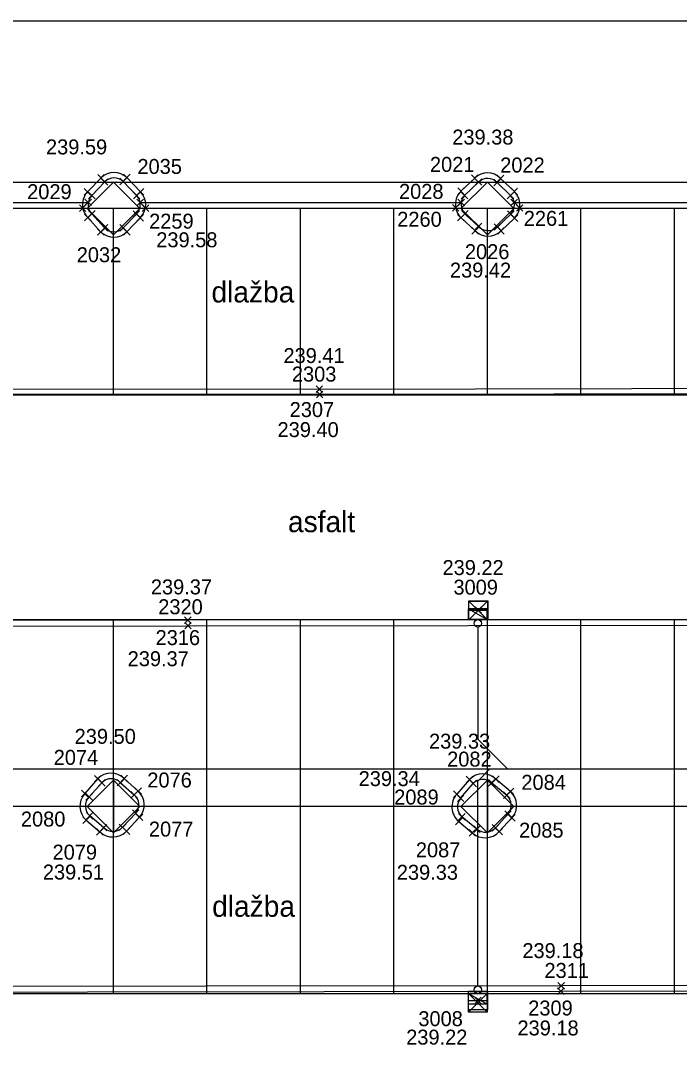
# Model space of a CAD drawing. Extents: x -264222 to -263676, y -1242344 to -1242060.
# Drawn here: x -264167.04 to -264149.44, y -1242214.48 to -1242186.47 of the extents above; entities that cross this region are included whole.
import ezdxf

# ---------------------------------------------------------------- set-up
doc = ezdxf.new("R2010")
doc.units = 0
for name, color, linetype in [('BODY_CISLO', 7, 'Continuous'), ('BODY_SYMBOL', 7, 'Continuous'), ('BODY_VYSKA', 7, 'Continuous'), ('BODY_VYSKY_UV', 7, 'Continuous'), ('KOORDINACNA_SITUACIA_DSP', 7, 'Continuous'), ('POPIS', 7, 'Continuous'), ('PROJEKT_DRS_OBRUBNIKY_KOMUNIKACIE', 7, 'Continuous'), ('PROJEKT_DRS_TDZ_VODOROVNE', 7, 'Continuous'), ('PROJEKT_DRS_UV_STAVBY', 7, 'Continuous'), ('RAM_NA_TLAC_8xA4_1-200', 7, 'Continuous'), ('SO_20-3_OBRUBNIKY_DOLNA_HRANA', 7, 'Continuous'), ('SO_20-3_OBRUBNIKY_HORNA_HRANA', 7, 'Continuous'), ('ULICNA_VPUST_POKLOP', 7, 'Continuous')]:
    doc.layers.add(name, color=color, linetype=linetype)

msp = doc.modelspace()

# ---------------------------------------------------------------- linework, layer by layer
at = {"layer": 'BODY_SYMBOL'}
for p, q in [((-264164.988, -1242190.754), (-264164.812, -1242190.578)), ((-264164.812, -1242190.754), (-264164.988, -1242190.578)), ((-264164.892, -1242190.863), (-264164.716, -1242190.687)), ((-264164.716, -1242190.863), (-264164.892, -1242190.687)), ((-264164.393, -1242190.851), (-264164.217, -1242190.675)), ((-264164.217, -1242190.851), (-264164.393, -1242190.675)), ((-264164.298, -1242190.745), (-264164.122, -1242190.569)), ((-264164.122, -1242190.745), (-264164.298, -1242190.569)), ((-264154.996, -1242190.758), (-264154.82, -1242190.582)), ((-264154.82, -1242190.758), (-264154.996, -1242190.582)), ((-264154.892, -1242190.863), (-264154.716, -1242190.687)), ((-264154.716, -1242190.863), (-264154.892, -1242190.687)), ((-264154.392, -1242190.876), (-264154.216, -1242190.7)), ((-264154.216, -1242190.876), (-264154.392, -1242190.7)), ((-264154.303, -1242190.766), (-264154.127, -1242190.59)), ((-264154.127, -1242190.766), (-264154.303, -1242190.59)), ((-264165.349, -1242191.127), (-264165.173, -1242190.951)), ((-264165.173, -1242191.127), (-264165.349, -1242190.951)), ((-264165.234, -1242191.224), (-264165.058, -1242191.048)), ((-264165.058, -1242191.224), (-264165.234, -1242191.048)), ((-264164.036, -1242191.224), (-264163.86, -1242191.048)), ((-264163.86, -1242191.224), (-264164.036, -1242191.048)), ((-264163.933, -1242191.128), (-264163.757, -1242190.952)), ((-264163.757, -1242191.128), (-264163.933, -1242190.952)), ((-264155.362, -1242191.109), (-264155.186, -1242190.933)), ((-264155.186, -1242191.109), (-264155.362, -1242190.933)), ((-264155.265, -1242191.225), (-264155.089, -1242191.049)), ((-264155.089, -1242191.225), (-264155.265, -1242191.049)), ((-264154.037, -1242191.223), (-264153.861, -1242191.047)), ((-264153.861, -1242191.223), (-264154.037, -1242191.047)), ((-264153.935, -1242191.12), (-264153.759, -1242190.944)), ((-264153.759, -1242191.12), (-264153.935, -1242190.944)), ((-264165.48, -1242191.56), (-264165.304, -1242191.384)), ((-264165.304, -1242191.56), (-264165.48, -1242191.384)), ((-264165.329, -1242191.407), (-264165.153, -1242191.231)), ((-264165.153, -1242191.407), (-264165.329, -1242191.231)), ((-264163.942, -1242191.412), (-264163.766, -1242191.236)), ((-264163.766, -1242191.412), (-264163.942, -1242191.236)), ((-264163.802, -1242191.56), (-264163.626, -1242191.384)), ((-264163.626, -1242191.56), (-264163.802, -1242191.384)), ((-264155.504, -1242191.556), (-264155.328, -1242191.38)), ((-264155.328, -1242191.556), (-264155.504, -1242191.38)), ((-264155.355, -1242191.41), (-264155.179, -1242191.234)), ((-264155.179, -1242191.41), (-264155.355, -1242191.234)), ((-264153.939, -1242191.408), (-264153.763, -1242191.232)), ((-264153.763, -1242191.408), (-264153.939, -1242191.232)), ((-264153.793, -1242191.558), (-264153.617, -1242191.382)), ((-264153.617, -1242191.558), (-264153.793, -1242191.382)), ((-264165.344, -1242191.815), (-264165.168, -1242191.639)), ((-264165.168, -1242191.815), (-264165.344, -1242191.639)), ((-264165.237, -1242191.713), (-264165.061, -1242191.537)), ((-264165.061, -1242191.713), (-264165.237, -1242191.537)), ((-264164.044, -1242191.719), (-264163.868, -1242191.543)), ((-264163.868, -1242191.719), (-264164.044, -1242191.543)), ((-264163.938, -1242191.821), (-264163.762, -1242191.645)), ((-264163.762, -1242191.821), (-264163.938, -1242191.645)), ((-264155.364, -1242191.816), (-264155.188, -1242191.64)), ((-264155.188, -1242191.816), (-264155.364, -1242191.64)), ((-264155.257, -1242191.715), (-264155.081, -1242191.539)), ((-264155.081, -1242191.715), (-264155.257, -1242191.539)), ((-264154.032, -1242191.721), (-264153.856, -1242191.545)), ((-264153.856, -1242191.721), (-264154.032, -1242191.545)), ((-264153.934, -1242191.828), (-264153.758, -1242191.652)), ((-264153.758, -1242191.828), (-264153.934, -1242191.652)), ((-264164.892, -1242192.092), (-264164.716, -1242191.916)), ((-264164.716, -1242192.092), (-264164.892, -1242191.916)), ((-264164.399, -1242192.091), (-264164.223, -1242191.915)), ((-264164.223, -1242192.091), (-264164.399, -1242191.915)), ((-264154.895, -1242192.049), (-264154.719, -1242191.873)), ((-264154.719, -1242192.049), (-264154.895, -1242191.873)), ((-264154.388, -1242192.066), (-264154.212, -1242191.89)), ((-264154.212, -1242192.066), (-264154.388, -1242191.89)), ((-264164.991, -1242192.201), (-264164.815, -1242192.025)), ((-264164.815, -1242192.201), (-264164.991, -1242192.025)), ((-264164.3, -1242192.195), (-264164.124, -1242192.019)), ((-264164.124, -1242192.195), (-264164.3, -1242192.019)), ((-264154.984, -1242192.166), (-264154.808, -1242191.99)), ((-264154.808, -1242192.166), (-264154.984, -1242191.99)), ((-264154.291, -1242192.172), (-264154.115, -1242191.996)), ((-264154.115, -1242192.172), (-264154.291, -1242191.996)), ((-264159.15, -1242196.404), (-264158.974, -1242196.228)), ((-264158.974, -1242196.404), (-264159.15, -1242196.228)), ((-264159.141, -1242196.548), (-264158.965, -1242196.372)), ((-264158.965, -1242196.548), (-264159.141, -1242196.372)), ((-264154.898, -1242202.314), (-264154.722, -1242202.138)), ((-264154.722, -1242202.314), (-264154.898, -1242202.138)), ((-264162.666, -1242202.588), (-264162.49, -1242202.412)), ((-264162.49, -1242202.588), (-264162.666, -1242202.412)), ((-264162.663, -1242202.733), (-264162.487, -1242202.557)), ((-264162.487, -1242202.733), (-264162.663, -1242202.557)), ((-264165.074, -1242206.825), (-264164.898, -1242206.649)), ((-264164.898, -1242206.825), (-264165.074, -1242206.649)), ((-264164.97, -1242206.937), (-264164.794, -1242206.761)), ((-264164.794, -1242206.937), (-264164.97, -1242206.761)), ((-264164.466, -1242206.933), (-264164.29, -1242206.757)), ((-264164.29, -1242206.933), (-264164.466, -1242206.757)), ((-264164.371, -1242206.819), (-264164.195, -1242206.643)), ((-264164.195, -1242206.819), (-264164.371, -1242206.643)), ((-264155.134, -1242206.846), (-264154.958, -1242206.67)), ((-264154.958, -1242206.846), (-264155.134, -1242206.67)), ((-264155.035, -1242206.954), (-264154.859, -1242206.778)), ((-264154.859, -1242206.954), (-264155.035, -1242206.778)), ((-264154.541, -1242206.934), (-264154.365, -1242206.758)), ((-264154.365, -1242206.934), (-264154.541, -1242206.758)), ((-264154.427, -1242206.839), (-264154.251, -1242206.663)), ((-264154.251, -1242206.839), (-264154.427, -1242206.663)), ((-264165.425, -1242207.225), (-264165.249, -1242207.049)), ((-264165.249, -1242207.225), (-264165.425, -1242207.049)), ((-264163.997, -1242207.155), (-264163.821, -1242206.979)), ((-264163.821, -1242207.155), (-264163.997, -1242206.979)), ((-264155.475, -1242207.239), (-264155.299, -1242207.063)), ((-264155.299, -1242207.239), (-264155.475, -1242207.063)), ((-264154.041, -1242207.164), (-264153.865, -1242206.988)), ((-264153.865, -1242207.164), (-264154.041, -1242206.988)), ((-264165.307, -1242207.311), (-264165.131, -1242207.135)), ((-264165.131, -1242207.311), (-264165.307, -1242207.135)), ((-264164.105, -1242207.255), (-264163.929, -1242207.079)), ((-264163.929, -1242207.255), (-264164.105, -1242207.079)), ((-264155.371, -1242207.35), (-264155.195, -1242207.174)), ((-264155.195, -1242207.35), (-264155.371, -1242207.174)), ((-264154.139, -1242207.269), (-264153.963, -1242207.093)), ((-264153.963, -1242207.269), (-264154.139, -1242207.093)), ((-264164.061, -1242207.75), (-264163.885, -1242207.574)), ((-264163.885, -1242207.75), (-264164.061, -1242207.574)), ((-264154.105, -1242207.773), (-264153.929, -1242207.597)), ((-264153.929, -1242207.773), (-264154.105, -1242207.597)), ((-264165.384, -1242207.936), (-264165.208, -1242207.76)), ((-264165.208, -1242207.936), (-264165.384, -1242207.76)), ((-264165.292, -1242207.819), (-264165.116, -1242207.643)), ((-264165.116, -1242207.819), (-264165.292, -1242207.643)), ((-264163.96, -1242207.859), (-264163.784, -1242207.683)), ((-264163.784, -1242207.859), (-264163.96, -1242207.683)), ((-264155.422, -1242207.969), (-264155.246, -1242207.793)), ((-264155.246, -1242207.969), (-264155.422, -1242207.793)), ((-264155.34, -1242207.844), (-264155.164, -1242207.668)), ((-264155.164, -1242207.844), (-264155.34, -1242207.668)), ((-264153.998, -1242207.872), (-264153.822, -1242207.696)), ((-264153.822, -1242207.872), (-264153.998, -1242207.696)), ((-264165.018, -1242208.248), (-264164.842, -1242208.072)), ((-264164.842, -1242208.248), (-264165.018, -1242208.072)), ((-264164.918, -1242208.135), (-264164.742, -1242207.959)), ((-264164.742, -1242208.135), (-264164.918, -1242207.959)), ((-264164.415, -1242208.126), (-264164.239, -1242207.95)), ((-264164.239, -1242208.126), (-264164.415, -1242207.95)), ((-264164.309, -1242208.232), (-264164.133, -1242208.056)), ((-264164.133, -1242208.232), (-264164.309, -1242208.056)), ((-264155.059, -1242208.275), (-264154.883, -1242208.099)), ((-264154.883, -1242208.275), (-264155.059, -1242208.099)), ((-264154.934, -1242208.176), (-264154.758, -1242208)), ((-264154.758, -1242208.176), (-264154.934, -1242208)), ((-264154.442, -1242208.14), (-264154.266, -1242207.964)), ((-264154.266, -1242208.14), (-264154.442, -1242207.964)), ((-264154.339, -1242208.242), (-264154.163, -1242208.066)), ((-264154.163, -1242208.242), (-264154.339, -1242208.066)), ((-264152.692, -1242212.513), (-264152.516, -1242212.337)), ((-264152.516, -1242212.513), (-264152.692, -1242212.337)), ((-264152.682, -1242212.369), (-264152.506, -1242212.193)), ((-264152.506, -1242212.369), (-264152.682, -1242212.193)), ((-264154.907, -1242212.762), (-264154.731, -1242212.586)), ((-264154.731, -1242212.762), (-264154.907, -1242212.586))]:
    msp.add_line(p, q, dxfattribs=at)
at = {"layer": 'KOORDINACNA_SITUACIA_DSP'}
for p, q in [((-264170.162, -1242190.775), (-264131.568, -1242190.775)), ((-264131.568, -1242191.482), (-264172.558, -1242191.482)), ((-264134.568, -1242191.482), (-264169.568, -1242191.482)), ((-264155.074, -1242202.192), (-264154.574, -1242202.192)), ((-264155.074, -1242202.482), (-264155.074, -1242202.192)), ((-264155.074, -1242202.192), (-264154.574, -1242202.482)), ((-264155.074, -1242202.192), (-264154.574, -1242202.482)), ((-264154.574, -1242202.192), (-264155.074, -1242202.192)), ((-264154.574, -1242202.192), (-264154.574, -1242202.482)), ((-264154.574, -1242202.482), (-264154.574, -1242202.192)), ((-264154.574, -1242202.482), (-264155.074, -1242202.482)), ((-264154.824, -1242202.682), (-264154.824, -1242205.68)), ((-264154.824, -1242205.68), (-264154.029, -1242206.476)), ((-264176.824, -1242206.476), (-264124.354, -1242206.476)), ((-264154.824, -1242206.801), (-264154.499, -1242206.476)), ((-264154.824, -1242212.282), (-264154.824, -1242206.801)), ((-264155.074, -1242212.482), (-264154.574, -1242212.482)), ((-264155.074, -1242212.772), (-264155.074, -1242212.482)), ((-264155.074, -1242212.482), (-264154.574, -1242212.772)), ((-264155.074, -1242212.482), (-264154.574, -1242212.772)), ((-264154.574, -1242212.482), (-264155.074, -1242212.482)), ((-264154.574, -1242212.482), (-264154.574, -1242212.772)), ((-264154.574, -1242212.772), (-264154.574, -1242212.482)), ((-264154.574, -1242212.772), (-264155.074, -1242212.772))]:
    msp.add_line(p, q, dxfattribs=at)
for points in [[(-264164.568, -1242190.775), (-264163.861, -1242191.482), (-264164.568, -1242192.189), (-264165.275, -1242191.482)], [(-264154.568, -1242190.775), (-264153.861, -1242191.482), (-264154.568, -1242192.189), (-264155.275, -1242191.482)], [(-264163.861, -1242207.482), (-264164.568, -1242206.775), (-264165.275, -1242207.482), (-264164.568, -1242208.189)], [(-264153.861, -1242207.482), (-264154.568, -1242206.775), (-264155.275, -1242207.482), (-264154.568, -1242208.189)]]:
    msp.add_lwpolyline(points, close=True, dxfattribs=at)
for points in [[(-264163.861, -1242191.482), (-264163.861, -1242191.482), (-264164.568, -1242192.189), (-264165.275, -1242191.482)], [(-264153.861, -1242191.482), (-264153.861, -1242191.482), (-264154.568, -1242192.189), (-264155.275, -1242191.482)]]:
    msp.add_lwpolyline(points, dxfattribs=at)
for centre in [(-264154.824, -1242202.582), (-264154.824, -1242212.382)]:
    msp.add_circle(centre, 0.1, dxfattribs=at)
at = {"layer": 'PROJEKT_DRS_OBRUBNIKY_KOMUNIKACIE'}
for p, q in [((-264170.162, -1242190.775), (-264131.568, -1242190.775)), ((-264131.568, -1242191.482), (-264172.558, -1242191.482)), ((-264134.568, -1242191.482), (-264169.568, -1242191.482)), ((-264134.568, -1242196.482), (-264170.068, -1242196.482)), ((-264184.568, -1242202.482), (-264134.568, -1242202.482)), ((-264164.568, -1242206.775), (-264165.275, -1242207.482)), ((-264163.861, -1242207.482), (-264164.568, -1242206.775)), ((-264164.568, -1242206.775), (-264164.568, -1242208.189)), ((-264164.568, -1242208.189), (-264164.568, -1242206.775)), ((-264154.568, -1242206.775), (-264155.275, -1242207.482)), ((-264153.861, -1242207.482), (-264154.568, -1242206.775)), ((-264154.568, -1242206.775), (-264154.568, -1242208.189)), ((-264154.568, -1242208.189), (-264154.568, -1242206.775)), ((-264165.275, -1242207.482), (-264164.568, -1242208.189)), ((-264164.568, -1242208.189), (-264163.861, -1242207.482)), ((-264155.275, -1242207.482), (-264154.568, -1242208.189)), ((-264154.568, -1242208.189), (-264153.861, -1242207.482)), ((-264182.068, -1242212.482), (-264134.568, -1242212.482))]:
    msp.add_line(p, q, dxfattribs=at)
for points in [[(-264164.568, -1242190.775), (-264163.861, -1242191.482), (-264164.568, -1242192.189), (-264165.275, -1242191.482), (-264164.568, -1242190.775)], [(-264154.568, -1242190.775), (-264153.861, -1242191.482), (-264154.568, -1242192.189), (-264155.275, -1242191.482), (-264154.568, -1242190.775)], [(-264163.861, -1242191.482), (-264164.568, -1242192.189), (-264165.275, -1242191.482)], [(-264153.861, -1242191.482), (-264154.568, -1242192.189), (-264155.275, -1242191.482)]]:
    msp.add_lwpolyline(points, dxfattribs=at)
at = {"layer": 'PROJEKT_DRS_TDZ_VODOROVNE'}
for p, q in [((-264164.568, -1242196.482), (-264164.568, -1242191.482)), ((-264162.068, -1242196.482), (-264162.068, -1242191.482)), ((-264159.568, -1242196.482), (-264159.568, -1242191.482)), ((-264157.068, -1242196.482), (-264157.068, -1242191.482)), ((-264154.568, -1242196.482), (-264154.568, -1242191.482)), ((-264152.068, -1242196.482), (-264152.068, -1242191.482)), ((-264149.568, -1242196.482), (-264149.568, -1242191.482)), ((-264164.568, -1242207.482), (-264164.568, -1242202.482)), ((-264162.068, -1242207.482), (-264162.068, -1242202.482)), ((-264159.568, -1242207.482), (-264159.568, -1242202.482)), ((-264157.068, -1242207.482), (-264157.068, -1242202.482)), ((-264154.568, -1242207.482), (-264154.568, -1242202.482)), ((-264152.068, -1242207.482), (-264152.068, -1242202.482)), ((-264149.568, -1242207.482), (-264149.568, -1242202.482)), ((-264134.568, -1242207.482), (-264184.568, -1242207.482)), ((-264134.568, -1242207.482), (-264175.568, -1242207.482)), ((-264164.568, -1242212.482), (-264164.568, -1242207.482)), ((-264162.068, -1242212.482), (-264162.068, -1242207.482)), ((-264159.568, -1242212.482), (-264159.568, -1242207.482)), ((-264157.068, -1242212.482), (-264157.068, -1242207.482)), ((-264154.568, -1242212.482), (-264154.568, -1242207.482)), ((-264152.068, -1242212.482), (-264152.068, -1242207.482)), ((-264149.568, -1242212.482), (-264149.568, -1242207.482))]:
    msp.add_line(p, q, dxfattribs=at)
at = {"layer": 'PROJEKT_DRS_UV_STAVBY'}
for points in [[(-264155.068, -1242202.489), (-264155.068, -1242201.989), (-264154.568, -1242201.989), (-264154.568, -1242202.489), (-264155.068, -1242202.489), (-264154.568, -1242201.989), (-264155.068, -1242201.989), (-264154.568, -1242202.489)], [(-264155.074, -1242212.982), (-264155.074, -1242212.482), (-264154.574, -1242212.482), (-264154.574, -1242212.982), (-264155.074, -1242212.982), (-264154.574, -1242212.482), (-264155.074, -1242212.482), (-264154.574, -1242212.982)]]:
    msp.add_lwpolyline(points, dxfattribs=at)
at = {"layer": 'RAM_NA_TLAC_8xA4_1-200'}
msp.add_lwpolyline([(-264222.03, -1242186.466), (-264054.03, -1242186.466), (-264054.03, -1242305.266), (-264222.03, -1242305.266)], close=True, dxfattribs=at)
at = {"layer": 'SO_20-3_OBRUBNIKY_DOLNA_HRANA'}
for p, q in [((-264165.261, -1242191.039), (-264164.9, -1242190.666)), ((-264164.21, -1242190.657), (-264163.845, -1242191.04)), ((-264155.274, -1242191.021), (-264154.908, -1242190.67)), ((-264154.215, -1242190.678), (-264153.847, -1242191.032)), ((-264163.714, -1242191.472), (-264155.416, -1242191.468)), ((-264153.705, -1242191.47), (-264145.403, -1242191.476)), ((-264164.903, -1242192.113), (-264165.256, -1242191.727)), ((-264163.85, -1242191.733), (-264164.212, -1242192.107)), ((-264154.896, -1242192.078), (-264155.276, -1242191.728)), ((-264153.846, -1242191.74), (-264154.203, -1242192.084)), ((-264164.986, -1242206.737), (-264165.337, -1242207.137)), ((-264163.909, -1242207.067), (-264164.283, -1242206.731)), ((-264155.046, -1242206.758), (-264155.387, -1242207.151)), ((-264153.953, -1242207.076), (-264154.339, -1242206.751)), ((-264165.296, -1242207.848), (-264164.93, -1242208.16)), ((-264164.221, -1242208.144), (-264163.872, -1242207.771)), ((-264155.334, -1242207.881), (-264154.971, -1242208.187)), ((-264154.251, -1242208.154), (-264153.91, -1242207.784))]:
    msp.add_line(p, q, dxfattribs=at)
for points in [[(-264169.573, -1242195.968), (-264169.543, -1242191.482), (-264165.392, -1242191.472)], [(-264134.111, -1242196.42), (-264146.541, -1242196.439), (-264159.053, -1242196.46), (-264170.082, -1242196.449)], [(-264169.718, -1242196.306), (-264159.062, -1242196.316), (-264146.532, -1242196.293), (-264134.448, -1242196.268)], [(-264134.11, -1242202.476), (-264147.578, -1242202.485), (-264162.578, -1242202.5), (-264185.058, -1242202.528)], [(-264184.725, -1242202.666), (-264162.575, -1242202.645), (-264147.576, -1242202.628), (-264134.442, -1242202.625)], [(-264182.566, -1242212.438), (-264171.604, -1242212.447), (-264152.604, -1242212.425), (-264134.055, -1242212.391)], [(-264134.418, -1242212.255), (-264152.594, -1242212.281), (-264171.607, -1242212.3), (-264182.247, -1242212.302)]]:
    msp.add_lwpolyline(points, dxfattribs=at)
for centre, major_axis, ratio, start_param, end_param in [((-264164.55, -1242191.019), (-0.119, 0.482), 0.99991, 5.285859, 6.822326), ((-264154.565, -1242191.023), (-0.185, 0.456), 0.998748, 5.103195, 6.668379), ((-264164.915, -1242191.38), (-0.006, -0.486), 0.997433, 3.947174, 5.518203), ((-264164.201, -1242191.384), (0.07, -0.49), 0.999575, 0.646619, 2.19673), ((-264154.933, -1242191.375), (0.04, -0.49), 0.999431, 3.826507, 5.43039), ((-264154.194, -1242191.386), (-0.061, 0.492), 0.999933, 3.794834, 5.384472), ((-264164.561, -1242191.757), (-0.492, -0.045), 0.999378, 0.714186, 2.263033), ((-264154.546, -1242191.73), (0.057, -0.49), 0.999729, 5.380379, 6.937386), ((-264164.632, -1242207.086), (-0.405, -0.29), 0.998526, 3.313807, 4.882779), ((-264154.689, -1242207.11), (-0.361, -0.348), 0.999457, 3.173462, 4.737413), ((-264164.247, -1242207.438), (-0.066, 0.498), 0.999345, 3.855603, 5.412262), ((-264154.288, -1242207.452), (-0.214, 0.456), 0.999993, 3.552487, 5.116074), ((-264164.958, -1242207.472), (-0.377, -0.337), 0.99987, 4.829572, 6.39205), ((-264155.008, -1242207.49), (-0.078, -0.503), 0.999834, 4.136108, 5.742051), ((-264164.584, -1242207.791), (0.486, -0.144), 0.999137, 4.247319, 5.798264), ((-264154.628, -1242207.808), (0.415, -0.298), 0.999188, 4.598411, 6.163316)]:
    msp.add_ellipse(centre, major_axis=major_axis, ratio=ratio, start_param=start_param, end_param=end_param, dxfattribs=at)
at = {"layer": 'SO_20-3_OBRUBNIKY_HORNA_HRANA'}
for p, q in [((-264165.146, -1242191.136), (-264164.804, -1242190.775)), ((-264164.305, -1242190.763), (-264163.948, -1242191.136)), ((-264155.177, -1242191.137), (-264154.804, -1242190.775)), ((-264154.304, -1242190.788), (-264153.949, -1242191.135)), ((-264169.69, -1242191.329), (-264165.241, -1242191.319)), ((-264163.854, -1242191.324), (-264155.267, -1242191.322)), ((-264153.851, -1242191.32), (-264145.258, -1242191.329)), ((-264164.804, -1242192.004), (-264165.149, -1242191.625)), ((-264163.956, -1242191.631), (-264164.311, -1242192.003)), ((-264154.807, -1242191.961), (-264155.169, -1242191.627)), ((-264153.944, -1242191.633), (-264154.3, -1242191.978)), ((-264165.219, -1242207.223), (-264164.882, -1242206.849)), ((-264164.378, -1242206.845), (-264164.017, -1242207.167)), ((-264155.283, -1242207.262), (-264154.947, -1242206.866)), ((-264154.453, -1242206.846), (-264154.051, -1242207.181)), ((-264164.83, -1242208.047), (-264165.204, -1242207.731)), ((-264163.973, -1242207.662), (-264164.327, -1242208.038)), ((-264154.846, -1242208.088), (-264155.252, -1242207.756)), ((-264154.017, -1242207.685), (-264154.354, -1242208.052))]:
    msp.add_line(p, q, dxfattribs=at)
msp.add_arc((-264164.558, -1242191.763), 0.345, 224.4513, 315.7811, dxfattribs=at)
for centre, major_axis, ratio, start_param, end_param in [((-264164.548, -1242191.023), (-0.281, -0.22), 0.99964, 3.296879, 4.848151), ((-264154.561, -1242191.039), (-0.165, -0.319), 0.998072, 2.819872, 4.362748), ((-264164.896, -1242191.382), (-0.012, -0.351), 0.997133, 3.96982, 5.509012), ((-264164.201, -1242191.379), (0.278, 0.215), 0.99997, 4.826313, 6.390155), ((-264154.92, -1242191.378), (0.006, -0.352), 0.998726, 3.943695, 5.481083), ((-264154.201, -1242191.387), (0.068, 0.35), 0.999802, 4.141568, 5.68996), ((-264154.545, -1242191.716), (0.3, -0.197), 0.998792, 4.475644, 6.04586), ((-264164.629, -1242207.085), (-0.289, -0.193), 0.997405, 3.316497, 4.941811), ((-264154.69, -1242207.122), (-0.318, -0.176), 0.998534, 3.500095, 4.994891), ((-264164.958, -1242207.469), (-0.072, -0.352), 0.999075, 4.156349, 5.730166), ((-264164.229, -1242207.435), (-0.263, 0.219), 0.999964, 3.11009, 4.73871), ((-264155.016, -1242207.493), (0.094, -0.34), 0.999809, 3.727362, 5.281006), ((-264154.285, -1242207.45), (-0.095, 0.344), 0.999803, 3.72526, 5.297976), ((-264164.583, -1242207.791), (0.345, -0.089), 0.998646, 4.199122, 5.767175), ((-264154.619, -1242207.814), (0.095, -0.343), 0.999581, 5.318165, 6.851043)]:
    msp.add_ellipse(centre, major_axis=major_axis, ratio=ratio, start_param=start_param, end_param=end_param, dxfattribs=at)
at = {"layer": 'ULICNA_VPUST_POKLOP'}
for p, q in [((-264154.81, -1242202.226), (-264154.81, -1242202.226)), ((-264154.819, -1242212.674), (-264154.819, -1242212.674))]:
    msp.add_line(p, q, dxfattribs=at)
for points in [[(-264155.06, -1242202.226), (-264155.06, -1242201.976), (-264154.56, -1242201.976), (-264154.56, -1242202.476), (-264155.06, -1242202.476), (-264155.06, -1242202.226), (-264154.56, -1242202.226)], [(-264155.069, -1242212.674), (-264155.069, -1242212.424), (-264154.569, -1242212.424), (-264154.569, -1242212.924), (-264155.069, -1242212.924), (-264155.069, -1242212.674), (-264154.569, -1242212.674)]]:
    msp.add_lwpolyline(points, dxfattribs=at)

# ---------------------------------------------------------------- texts
at = {"layer": 'BODY_CISLO'}
for s, p in [('2035', (-264163.927, -1242190.559)), ('2021', (-264156.104, -1242190.504)), ('2022', (-264154.225, -1242190.521)), ('2029', (-264166.876, -1242191.234)), ('2028', (-264156.931, -1242191.226)), ('2259', (-264163.614, -1242192.023)), ('2260', (-264156.979, -1242191.972)), ('2261', (-264153.595, -1242191.948)), ('2026', (-264155.169, -1242192.839)), ('2032', (-264165.55, -1242192.921)), ('2303', (-264159.796, -1242196.114)), ('2307', (-264159.856, -1242197.063)), ('3009', (-264155.476, -1242201.814)), ('2320', (-264163.37, -1242202.338)), ('2316', (-264163.441, -1242203.163)), ('2074', (-264166.166, -1242206.367)), ('2082', (-264155.644, -1242206.414)), ('2076', (-264163.662, -1242206.973)), ('2084', (-264153.659, -1242207.035)), ('2089', (-264157.06, -1242207.429)), ('2080', (-264167.043, -1242208.017)), ('2077', (-264163.62, -1242208.286)), ('2085', (-264153.721, -1242208.315)), ('2087', (-264156.481, -1242208.841)), ('2079', (-264166.197, -1242208.903)), ('2311', (-264153.042, -1242212.068)), ('2309', (-264153.476, -1242213.073)), ('3008', (-264156.414, -1242213.358))]:
    msp.add_text(s, height=0.4, dxfattribs=at).set_placement(p)
at = {"layer": 'BODY_VYSKA'}
for s, p in [('239.38', (-264155.507, -1242189.773)), ('239.59', (-264166.372, -1242190.036)), ('239.58', (-264163.423, -1242192.521)), ('239.42', (-264155.569, -1242193.332)), ('239.41', (-264160.022, -1242195.618)), ('239.40', (-264160.18, -1242197.599)), ('239.37', (-264163.568, -1242201.807)), ('239.37', (-264164.188, -1242203.728)), ('239.50', (-264165.606, -1242205.806)), ('239.33', (-264156.129, -1242205.934)), ('239.34', (-264158.011, -1242206.936)), ('239.51', (-264166.456, -1242209.435)), ('239.33', (-264156.99, -1242209.441)), ('239.18', (-264153.632, -1242211.537)), ('239.18', (-264153.763, -1242213.606))]:
    msp.add_text(s, height=0.4, dxfattribs=at).set_placement(p)
at = {"layer": 'BODY_VYSKY_UV'}
for p in [(-264155.768, -1242201.289), (-264156.739, -1242213.852)]:
    msp.add_text('239.22', height=0.4, dxfattribs=at).set_placement(p)
at = {"layer": 'POPIS'}
for p in [(-264161.947, -1242193.998), (-264161.929, -1242210.433)]:
    msp.add_text('dlažba', height=0.5625, rotation=360, dxfattribs=at).set_placement(p)
msp.add_text('asfalt', height=0.5625, dxfattribs=at).set_placement((-264159.901, -1242200.143))

doc.saveas('drawing.dxf')
